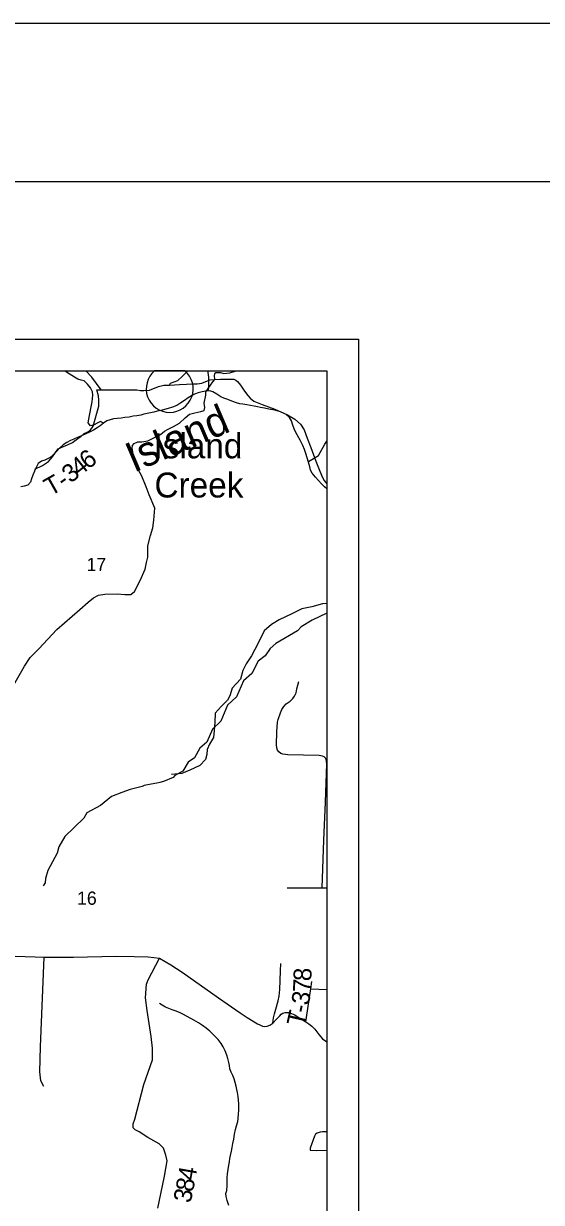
# Model space of a CAD drawing. Extents: x 0 to 34, y 0 to 22.
# Drawn here: x 7.939 to 9.58, y 18.266 to 22 of the extents above; entities that cross this region are included whole.
import ezdxf

# ---------------------------------------------------------------- set-up
doc = ezdxf.new("R2010")
doc.units = 0
for name, color, linetype in [('GM_X_County_Road', 7, 'Continuous'), ('GM_X_Minor_River', 7, 'Continuous'), ('GM_X_Minor_River_Text', 7, 'Continuous'), ('GM_X_Section_Text', 7, 'Continuous'), ('GM_X_State_Shield', 7, 'Continuous'), ('GM_X_Township_Road', 7, 'Continuous'), ('GM_X_Township_Road_Text', 7, 'Continuous'), ('GM_X_Unincorporated_Location', 7, 'Continuous'), ('GM_X_Unincorporated_Text', 7, 'Continuous'), ('SH_Border', 7, 'Continuous'), ('SH_Cut_Line', 7, 'Continuous'), ('SH_Data', 7, 'Continuous')]:
    doc.layers.add(name, color=color, linetype=linetype)

msp = doc.modelspace()

# ---------------------------------------------------------------- linework, layer by layer
at = {"layer": 'GM_X_County_Road'}
msp.add_line((8.1713, 20.8404), (8.1854, 20.8396), dxfattribs=at)
for points in [[(8.1854, 20.8396), (8.2981, 20.8398), (8.3096, 20.8379), (8.3205, 20.8375), (8.3376, 20.839), (8.3662, 20.85), (8.3833, 20.8546), (8.4012, 20.8545), (8.4336, 20.8573), (8.4552, 20.8584), (8.4744, 20.8591), (8.4894, 20.8594), (8.5044, 20.8609), (8.5171, 20.8658), (8.5299, 20.8711), (8.5448, 20.8731), (8.563, 20.8739), (8.605, 20.8736), (8.6119, 20.8708), (8.6165, 20.8666), (8.6268, 20.855), (8.639, 20.8362), (8.6495, 20.8222), (8.6574, 20.8131), (8.6689, 20.8044), (8.6947, 20.7939), (8.7349, 20.7783), (8.7756, 20.7607), (8.7989, 20.7471), (8.8171, 20.7307), (8.8281, 20.7129), (8.838, 20.6872), (8.8495, 20.6573), (8.8651, 20.6143), (8.8734, 20.5925), (8.8853, 20.5639), (8.8912, 20.5526), (8.9, 20.5417)], [(7.6225, 19.0416), (7.715, 19.0364), (7.7831, 19.0443), (7.8475, 19.048), (7.9757, 19.0435)], [(7.9757, 19.0435), (8.0046, 19.0425), (8.0967, 19.0433), (8.2313, 19.046), (8.2892, 19.0453), (8.3342, 19.0443), (8.3695, 19.0396)], [(8.3695, 19.0396), (8.4061, 19.0192), (8.4415, 18.9951), (8.5564, 18.9143), (8.6257, 18.8667), (8.648, 18.8521), (8.6804, 18.8318), (8.6882, 18.8282), (8.6964, 18.8248), (8.7034, 18.8234), (8.7114, 18.8239), (8.7196, 18.8271), (8.7292, 18.8338), (8.7407, 18.8462), (8.751, 18.8572), (8.7556, 18.8624), (8.7611, 18.8658), (8.7677, 18.8676), (8.7731, 18.8682), (8.78, 18.8679), (8.7877, 18.8649), (8.7986, 18.8599), (8.8058, 18.8555), (8.8194, 18.8464), (8.8337, 18.8383), (8.8433, 18.8314), (8.853, 18.8248), (8.8617, 18.8154), (8.8747, 18.7985), (8.8865, 18.7844), (8.9, 18.7753)]]:
    msp.add_lwpolyline(points, dxfattribs=at)
at = {"layer": 'GM_X_Minor_River'}
for points in [[(8.1928, 20.7347), (8.1829, 20.7395), (8.172, 20.7346), (8.1623, 20.7294), (8.1514, 20.7256), (8.1438, 20.7356), (8.1457, 20.7471), (8.148, 20.7586), (8.1504, 20.769), (8.1523, 20.7804), (8.1546, 20.7915), (8.1566, 20.8015), (8.1574, 20.8126), (8.1582, 20.8232), (8.1571, 20.8339), (8.1507, 20.8458), (8.1415, 20.8581), (8.1313, 20.8681), (8.1218, 20.8704), (8.1107, 20.8735), (8.1002, 20.8804), (8.0746, 20.8963), (8.0695, 20.9)], [(8.5241, 20.8365), (8.5259, 20.8466), (8.5263, 20.8584), (8.5264, 20.8687), (8.5261, 20.8785), (8.5254, 20.8888), (8.5232, 20.9)], [(8.9, 20.5261), (8.8926, 20.5327), (8.8832, 20.5427), (8.8738, 20.5523), (8.8639, 20.5634), (8.8537, 20.5757), (8.8488, 20.5858), (8.8466, 20.5956), (8.8423, 20.6107), (8.8377, 20.625), (8.8331, 20.6382), (8.8289, 20.651), (8.8236, 20.6638), (8.8155, 20.6803), (8.8022, 20.705), (8.7965, 20.7166), (8.7927, 20.7275), (8.7877, 20.7414), (8.7817, 20.7519), (8.7715, 20.7622), (8.7607, 20.7676), (8.7503, 20.7711), (8.7384, 20.7745), (8.7285, 20.7765), (8.7166, 20.7791), (8.7028, 20.7814), (8.6902, 20.7836), (8.6803, 20.7856), (8.6696, 20.7879), (8.6577, 20.7902), (8.647, 20.7922), (8.6344, 20.7941), (8.6241, 20.796), (8.6137, 20.7991), (8.5991, 20.8036), (8.586, 20.8089), (8.5737, 20.8135), (8.5641, 20.8181), (8.5516, 20.8261), (8.5392, 20.8337), (8.5289, 20.8372), (8.5156, 20.8352), (8.5046, 20.8334)], [(8.5046, 20.8334), (8.4926, 20.8307), (8.4809, 20.8258), (8.4712, 20.8205), (8.4611, 20.8149), (8.4488, 20.8061), (8.4369, 20.7985), (8.4246, 20.7905), (8.4107, 20.7847), (8.3968, 20.7805), (8.3859, 20.7775), (8.3749, 20.7749), (8.3628, 20.7722), (8.3515, 20.7696), (8.3311, 20.7651), (8.3202, 20.7625), (8.3104, 20.7599), (8.2979, 20.7576), (8.2861, 20.7561), (8.2737, 20.7538), (8.26, 20.7519), (8.2483, 20.75), (8.2358, 20.7488), (8.2237, 20.7477), (8.2131, 20.7451), (8.2033, 20.7421), (8.1925, 20.7345), (8.1818, 20.7262), (8.1721, 20.7194), (8.1605, 20.7126), (8.1478, 20.7061), (8.1358, 20.7004), (8.1227, 20.6943), (8.1125, 20.6901), (8.0987, 20.6836), (8.0882, 20.6791), (8.0758, 20.6734), (8.0646, 20.6662), (8.0532, 20.6552), (8.0421, 20.6434), (8.0325, 20.6344), (8.0229, 20.6261), (8.0064, 20.6172), (7.9959, 20.6138), (7.9851, 20.6062), (7.9786, 20.5939), (7.9733, 20.5823), (7.9684, 20.5699), (7.9638, 20.558), (7.9607, 20.548), (7.953, 20.5375), (7.9413, 20.5348), (7.9303, 20.533)], [(8.8417, 20.6127), (8.8736, 20.6315), (8.8941, 20.668), (8.9, 20.6769)], [(8.9, 20.1324), (8.8538, 20.1106), (8.819, 20.0895), (8.8075, 20.0768), (8.7383, 20.0364), (8.7204, 20.0205), (8.7042, 19.997), (8.6825, 19.9803), (8.6628, 19.9419), (8.6363, 19.9187), (8.6134, 19.8677), (8.5851, 19.8409), (8.5641, 19.7903), (8.5381, 19.7648), (8.5199, 19.7238), (8.4971, 19.7048), (8.481, 19.6744), (8.4608, 19.6608), (8.4436, 19.6323), (8.4181, 19.6186), (8.4129, 19.612), (8.3821, 19.5993), (8.3708, 19.5961), (8.3671, 19.5953), (8.3377, 19.5902), (8.3211, 19.5865), (8.3147, 19.5834), (8.2771, 19.5736), (8.2504, 19.5641), (8.2178, 19.5514), (8.1831, 19.5234), (8.1393, 19.5006), (8.1301, 19.4837), (8.0699, 19.4249), (8.0508, 19.3926), (8.0455, 19.3727), (8.0154, 19.3178), (8.009, 19.2918), (8.0074, 19.2789), (8.0011, 19.2689)], [(8.6063, 18.6576), (8.6026, 18.6686), (8.5973, 18.6783), (8.5932, 18.6892), (8.5917, 18.6994), (8.5891, 18.7092), (8.5861, 18.7217), (8.5831, 18.7323), (8.5777, 18.7466), (8.5712, 18.7593), (8.5648, 18.7697), (8.5557, 18.782), (8.5435, 18.7946), (8.5294, 18.8086), (8.5181, 18.8178), (8.506, 18.8265), (8.4929, 18.8352), (8.4785, 18.8436), (8.4576, 18.8551), (8.4441, 18.8623), (8.4333, 18.8673), (8.4195, 18.8725), (8.4099, 18.8757), (8.3991, 18.8799), (8.3891, 18.8842), (8.3782, 18.8907), (8.3693, 18.8961)], [(8.5895, 18.2565), (8.5841, 18.2723), (8.5807, 18.2851), (8.5804, 18.2946), (8.5827, 18.3042), (8.5842, 18.3183), (8.5837, 18.3324), (8.5838, 18.3438), (8.5857, 18.3564), (8.5875, 18.3702), (8.5894, 18.3843), (8.5913, 18.395), (8.5929, 18.405), (8.5945, 18.4145), (8.5979, 18.4283), (8.6002, 18.4402), (8.6024, 18.4532), (8.605, 18.467), (8.6076, 18.4823), (8.6109, 18.4972), (8.614, 18.5087), (8.6178, 18.5222), (8.619, 18.5321), (8.6201, 18.5458), (8.6208, 18.5584), (8.6216, 18.5687), (8.6217, 18.5782), (8.6191, 18.6013), (8.6172, 18.6138), (8.615, 18.6237), (8.6124, 18.6339), (8.6097, 18.6463), (8.6063, 18.6576)]]:
    msp.add_lwpolyline(points, dxfattribs=at)
at = {"layer": 'GM_X_State_Shield'}
msp.add_line((8.45, 20.9), (8.3542, 20.9), dxfattribs=at)
msp.add_arc((8.4021, 20.843), 0.0744, 130.0386, 49.9614, dxfattribs=at)
at = {"layer": 'GM_X_Township_Road'}
for p, q in [((8.5392, 20.8654), (8.5448, 20.8731)), ((8.1713, 20.8404), (8.1854, 20.8396)), ((8.8337, 18.8383), (8.8488, 18.9367)), ((8.8497, 18.9426), (8.9, 18.9402))]:
    msp.add_line(p, q, dxfattribs=at)
for points in [[(8.1854, 20.8396), (8.1549, 20.8803), (8.1361, 20.9)], [(8.4012, 20.8545), (8.4047, 20.8613), (8.4274, 20.8698), (8.4412, 20.8825), (8.4566, 20.8974), (8.458, 20.9)], [(8.5448, 20.8731), (8.5441, 20.8854), (8.5449, 20.8911), (8.5487, 20.8945), (8.5635, 20.8951), (8.5734, 20.8915), (8.5926, 20.8937), (8.6094, 20.8992), (8.6105, 20.9)], [(8.1037, 20.6806), (8.1054, 20.6818), (8.1112, 20.6861), (8.1219, 20.6935), (8.131, 20.7018), (8.1403, 20.7057), (8.1499, 20.711), (8.1598, 20.7248), (8.1776, 20.7887), (8.178, 20.8077), (8.1766, 20.8208), (8.1713, 20.8404)], [(8.3514, 20.4269), (8.3553, 20.465), (8.3368, 20.5071), (8.327, 20.5326), (8.3142, 20.5662), (8.2993, 20.5932), (8.2887, 20.6238), (8.2855, 20.6438), (8.2836, 20.6566), (8.284, 20.664), (8.2896, 20.6704), (8.301, 20.6751), (8.3134, 20.6757), (8.3325, 20.6783), (8.3516, 20.6875), (8.3733, 20.6984), (8.3853, 20.7093), (8.3975, 20.7149), (8.4145, 20.7236), (8.433, 20.7347), (8.4515, 20.751), (8.4644, 20.7624), (8.4815, 20.7668), (8.5005, 20.7708), (8.5116, 20.7748), (8.5139, 20.7842), (8.5118, 20.7978), (8.5161, 20.8232), (8.5165, 20.8339), (8.5392, 20.8654)], [(7.9752, 20.5882), (7.9985, 20.6002), (8.018, 20.6125), (8.0306, 20.6282), (8.0398, 20.6419), (8.0484, 20.653), (8.0655, 20.6602), (8.0777, 20.6653), (8.0937, 20.6732), (8.1037, 20.6806)], [(8.2646, 20.1917), (8.2792, 20.1915), (8.2907, 20.2009), (8.3082, 20.2355), (8.3245, 20.2714), (8.3291, 20.2932), (8.3323, 20.3101), (8.333, 20.3266), (8.3333, 20.3457), (8.3416, 20.3783), (8.349, 20.4031), (8.3514, 20.4269)], [(7.8992, 19.8904), (7.9418, 19.9644), (7.9599, 19.9919), (7.9877, 20.0201), (8.0444, 20.0812), (8.1172, 20.1445), (8.1436, 20.1669), (8.1608, 20.1811), (8.1761, 20.1897), (8.1968, 20.1929), (8.2361, 20.1935), (8.2597, 20.1918), (8.2646, 20.1917)], [(8.9, 20.1632), (8.8868, 20.1626), (8.8522, 20.1529), (8.8213, 20.1459), (8.7891, 20.1301), (8.7489, 20.1115), (8.725, 20.0967), (8.7015, 20.0765), (8.6821, 20.0378), (8.6612, 19.9975), (8.6443, 19.9718), (8.6337, 19.9507), (8.6266, 19.9236), (8.6006, 19.8946), (8.5923, 19.8709), (8.5854, 19.8567), (8.5649, 19.8374), (8.5464, 19.8162), (8.545, 19.7876), (8.5432, 19.761), (8.5405, 19.7385), (8.528, 19.7171), (8.5211, 19.701), (8.5195, 19.6846), (8.5156, 19.6693), (8.4974, 19.65), (8.4655, 19.635), (8.4408, 19.6247), (8.4075, 19.6211)], [(8.8854, 19.263), (8.8904, 19.414), (8.8954, 19.5339), (8.9, 19.6553), (8.8994, 19.6629), (8.898, 19.6687), (8.8956, 19.673), (8.8918, 19.677), (8.886, 19.68), (8.876, 19.6816), (8.7761, 19.6834), (8.7694, 19.6844), (8.7604, 19.6862), (8.7548, 19.6884), (8.7484, 19.6932), (8.744, 19.699), (8.7416, 19.7061), (8.7406, 19.7153), (8.742, 19.7572), (8.7442, 19.7875), (8.746, 19.7955), (8.7532, 19.817), (8.7578, 19.827), (8.7642, 19.8364), (8.7717, 19.8453), (8.7841, 19.8541), (8.7927, 19.8625), (8.7979, 19.8697), (8.8029, 19.88), (8.8052, 19.8928), (8.8112, 19.9161)], [(8.7739, 19.2621), (8.8513, 19.2628), (8.8673, 19.2629), (8.8854, 19.263), (8.9, 19.263)], [(8.0033, 18.6328), (7.9936, 18.6517), (7.9903, 18.6802), (7.9929, 18.7587), (8.0046, 19.0425)], [(8.2862, 18.5113), (8.2863, 18.5151), (8.2915, 18.5301), (8.3203, 18.6398), (8.3473, 18.718), (8.3473, 18.7551), (8.3431, 18.7921), (8.3304, 18.8738), (8.3252, 18.9143), (8.3289, 18.9574), (8.3338, 18.9708), (8.3695, 19.0396)], [(8.7292, 18.8338), (8.7309, 18.8506), (8.7342, 18.8635), (8.7383, 18.8782), (8.7457, 18.9046), (8.7489, 18.9198), (8.7514, 18.9403), (8.7526, 18.9686), (8.7534, 19), (8.7543, 19.0226)], [(8.8488, 18.9367), (8.8497, 18.9426), (8.8526, 18.9663)], [(8.3644, 18.248), (8.3739, 18.2934), (8.3856, 18.3492), (8.3939, 18.3977), (8.3895, 18.4163), (8.3822, 18.4376), (8.3691, 18.4512), (8.3333, 18.4714), (8.3049, 18.4895), (8.2929, 18.496), (8.286, 18.5026), (8.2862, 18.5113)], [(8.9, 18.4898), (8.8863, 18.4895), (8.8785, 18.4891), (8.8699, 18.4859), (8.8647, 18.4822), (8.8609, 18.4757), (8.8474, 18.4377), (8.8469, 18.4313), (8.8665, 18.4311), (8.9, 18.432)]]:
    msp.add_lwpolyline(points, dxfattribs=at)
at = {"layer": 'GM_X_Unincorporated_Location'}
msp.add_line((8.4021, 20.843), (8.4021, 20.843), dxfattribs=at)
at = {"layer": 'SH_Border'}
msp.add_lwpolyline([(1.5, 21.5), (33.5, 21.5), (33.5, 0.5), (1.5, 0.5)], close=True, dxfattribs=at)
at = {"layer": 'SH_Cut_Line'}
msp.add_lwpolyline([(0, 0), (34, 0), (34, 22), (0, 22)], close=True, dxfattribs=at)
at = {"layer": 'SH_Data'}
for p, q in [((2, 21), (9, 21)), ((9, 21), (9, 14))]:
    msp.add_line(p, q, dxfattribs=at)
msp.add_lwpolyline([(2.1, 20.9), (8.9, 20.9), (8.9, 14.1), (2.1, 14.1)], close=True, dxfattribs=at)

# ---------------------------------------------------------------- texts
at = {"layer": 'GM_X_Minor_River_Text'}
msp.add_text('Island', height=0.09472, rotation=23.1154, dxfattribs=at).set_placement((8.2884, 20.5769))
at = {"layer": 'GM_X_Section_Text'}
for s, p in [('17', (8.1385, 20.2658)), ('16', (8.1085, 19.209))]:
    msp.add_text(s, height=0.04186, rotation=0, dxfattribs=at).set_placement(p)
at = {"layer": 'GM_X_Township_Road_Text'}
for s, rotation, p in [('6', 37.3788, (8.1428, 20.5858)), ('4', 38.6208, (8.1158, 20.5642)), ('T', 29.418, (8.0242, 20.5022)), ('3', 38.6367, (8.0884, 20.5423)), ('-', 35.8589, (8.0671, 20.5269)), ('8', 88.0149, (8.8508, 18.9663)), ('7', 87.8139, (8.8494, 18.9311)), ('3', 80.2124, (8.8426, 18.8885)), ('T', 77.1955, (8.8275, 18.821)), ('-', 77.5076, (8.837, 18.8628)), ('4', 79.9925, (8.4825, 18.3324)), ('8', 78.7514, (8.4755, 18.2968)), ('3', 78.3461, (8.4683, 18.2621))]:
    msp.add_text(s, height=0.0568, rotation=rotation, dxfattribs=at).set_placement(p)
at = {"layer": 'GM_X_Unincorporated_Text'}
for s, p in [('Island', (8.3506, 20.623)), ('Creek', (8.3539, 20.4989))]:
    msp.add_text(s, height=0.07898, rotation=0, dxfattribs=at).set_placement(p)

doc.saveas('drawing.dxf')
